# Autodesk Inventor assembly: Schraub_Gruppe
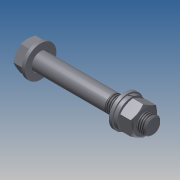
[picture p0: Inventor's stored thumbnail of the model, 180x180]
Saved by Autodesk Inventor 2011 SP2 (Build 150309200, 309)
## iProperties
Created: 2012-06
Part Number: Schraub_Gruppe
Document SubType Name: Assembly
Designer: JRE
Author: JRE
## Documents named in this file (5)
- E:\Users\jre\Documents\Inventor\Test\Schraub_Gruppe.iam
- C:\Users\JRE\Documents\Inventor\Content Center Files\R2011\de-DE\DIN 125-1  A\DIN 125 - A 17.ipt
- C:\Users\JRE\Documents\Inventor\Content Center Files\R2011\de-DE\DIN 127 - W\DIN 127 - A 16.ipt
- C:\Users\JRE\Documents\Inventor\Content Center Files\R2011\de-DE\DIN 934\DIN 934 - M16 x 2.ipt
- C:\Users\JRE\Documents\Inventor\Content Center Files\R2011\de-DE\DIN 931-1\DIN 931-1 - M16 x 110.ipt
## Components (5 placed, 4 different names)
1. DIN 125-1 A A 17:1 — Einfügen:3, Einfügen:4
2. DIN 125-1 A A 17:2 — Einfügen:2, Einfügen:3
3. DIN 127 - zurückgezogen A 16:1 — Einfügen:1, Einfügen:2
4. DIN 934 - ersetzt durch DIN EN 24032/28673/28674 M16:1 — Einfügen:1
5. DIN 931-1 - ersetzt durch DIN EN 24014 M16 x 110:1 — Einfügen:4
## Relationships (4: Insert 4)
- Einfügen:1 [Insert]: DIN 127 - zurückgezogen A 16:1 ↔ DIN 934 - ersetzt durch DIN EN 24032/28673/28674 M16:1
- Einfügen:2 [Insert]: DIN 125-1 A A 17:2 ↔ DIN 127 - zurückgezogen A 16:1
- Einfügen:3 [Insert]: DIN 125-1 A A 17:1 ↔ DIN 125-1 A A 17:2
- Einfügen:4 [Insert]: DIN 125-1 A A 17:1 ↔ DIN 931-1 - ersetzt durch DIN EN 24014 M16 x 110:1
